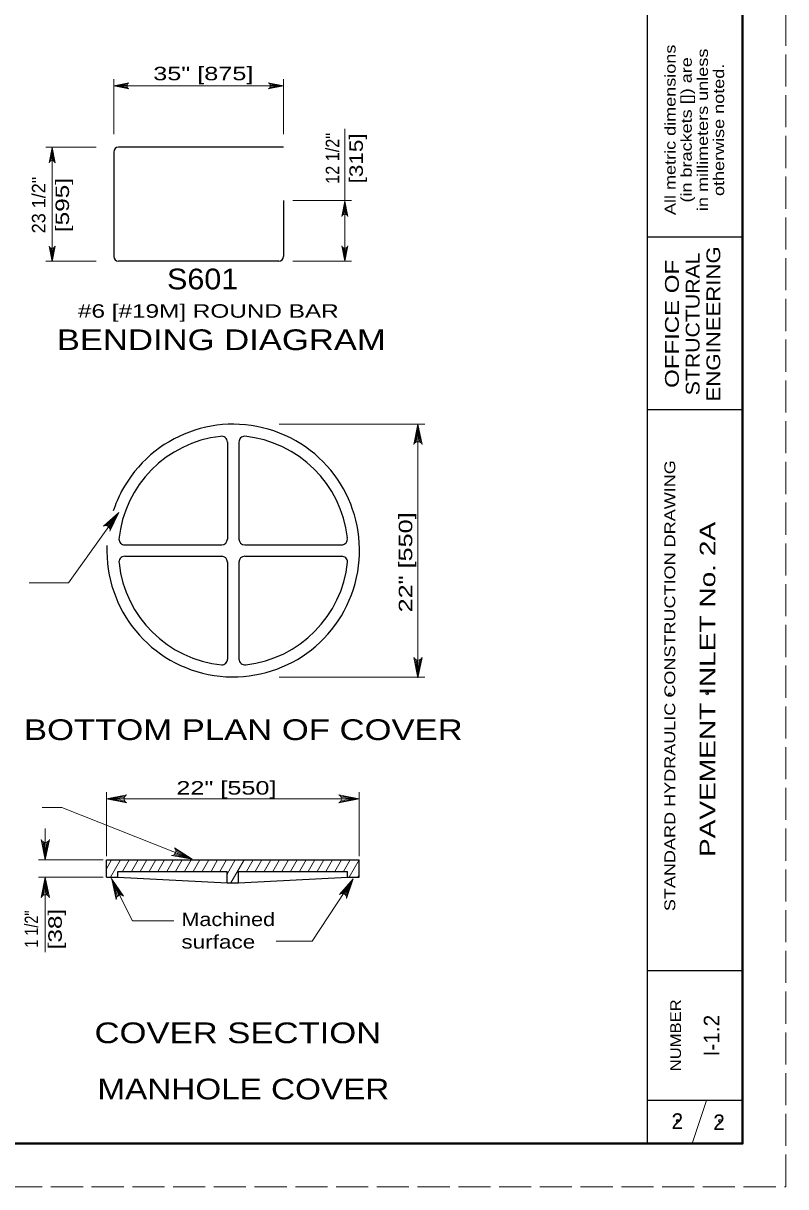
# Model space of a CAD drawing. Extents: x 758.3 to 792.3, y 849.7 to 893.7.
# Drawn here: x 783.49 to 792.32, y 849.69 to 863.16 of the extents above; entities that cross this region are included whole.
import ezdxf
from ezdxf.enums import TextEntityAlignment as Align

# ---------------------------------------------------------------- set-up
doc = ezdxf.new("R2010")
doc.units = 0
doc.header["$LTSCALE"] = 0.062
doc.header["$PDMODE"] = 32
doc.header["$PDSIZE"] = 0.031
doc.linetypes.add('LONG_DASHED', pattern=[7.5, 6, -1.5])
doc.layers.add('1', color=7, linetype='Continuous', lineweight=13)

msp = doc.modelspace()

# ---------------------------------------------------------------- linework, layer by layer
at = {"layer": '1', "lineweight": 25}
for p, q in [((790.7205, 850.18817), (790.7205, 871.18817)), ((791.8205, 871.18817), (791.8205, 850.18817)), ((786.50367, 861.72917), (784.59208, 861.72917)), ((784.53583, 861.67292), (784.53583, 860.46425)), ((786.50367, 861.11075), (786.50367, 860.46425)), ((791.8205, 860.68817), (790.7205, 860.68817)), ((786.44742, 860.40808), (784.59208, 860.40808)), ((791.8205, 858.68817), (790.7205, 858.68817)), ((785.85358, 858.314), (785.85358, 857.19033)), ((785.98658, 858.314), (785.98658, 857.1905)), ((784.66325, 857.12375), (785.78708, 857.12375)), ((786.05308, 857.12375), (787.17683, 857.12375)), ((784.66325, 856.99075), (785.78708, 856.99075)), ((786.05308, 856.99075), (787.17683, 856.99075)), ((785.85358, 856.92425), (785.85358, 855.80067)), ((785.98658, 856.92425), (785.98658, 855.80067)), ((784.45175, 853.27367), (784.45175, 853.47325)), ((784.45175, 853.47325), (787.37858, 853.47325)), ((787.37858, 853.27367), (787.37858, 853.47325)), ((784.45175, 853.27367), (784.58483, 853.27367)), ((784.58483, 853.27367), (784.58483, 853.34025)), ((784.58483, 853.34025), (785.84867, 853.34025)), ((784.58483, 853.27367), (785.84867, 853.20717)), ((785.84867, 853.20717), (785.84867, 853.34025)), ((785.98167, 853.20717), (785.98167, 853.34025)), ((785.98167, 853.34025), (787.2455, 853.34025)), ((785.98167, 853.20717), (787.2455, 853.27367)), ((787.2455, 853.27367), (787.2455, 853.34025)), ((787.2455, 853.27367), (787.37858, 853.27367)), ((785.84867, 853.20717), (785.98167, 853.20717)), ((791.8205, 852.18817), (790.7205, 852.18817)), ((791.8205, 850.68817), (790.7205, 850.68817))]:
    msp.add_line(p, q, dxfattribs=at)
at = {"layer": '1'}
for p, q in [((784.53583, 862.51583), (784.53583, 861.879)), ((786.50367, 862.51583), (786.50367, 861.879)), ((784.69608, 862.4625), (784.53583, 862.44008)), ((784.69067, 862.45142), (784.53583, 862.44008)), ((784.689, 862.44008), (784.53583, 862.44008)), ((784.69183, 862.42567), (784.53583, 862.44008)), ((784.698, 862.41533), (784.53583, 862.44008)), ((786.34158, 862.41533), (786.50367, 862.44008)), ((786.34342, 862.4625), (786.50367, 862.44008)), ((786.34767, 862.42567), (786.50367, 862.44008)), ((786.34883, 862.45142), (786.50367, 862.44008)), ((786.3505, 862.44008), (786.50367, 862.44008)), ((787.21333, 861.94258), (787.21333, 860.57067)), ((784.33358, 861.72917), (783.74917, 861.72917)), ((783.79758, 861.56442), (783.82233, 861.72658)), ((783.80792, 861.57058), (783.82233, 861.72658)), ((783.82233, 861.72658), (783.82233, 860.90492)), ((783.82233, 861.57342), (783.82233, 861.72658)), ((783.83367, 861.57175), (783.82233, 861.72658)), ((783.84475, 861.56633), (783.82233, 861.72658)), ((787.29033, 861.11075), (786.61192, 861.11075)), ((787.18858, 860.94342), (787.21333, 861.1055)), ((787.199, 860.9495), (787.21333, 861.1055)), ((787.21333, 860.95233), (787.21333, 861.1055)), ((787.22467, 860.95075), (787.21333, 861.1055)), ((787.23575, 860.94525), (787.21333, 861.1055)), ((783.82233, 860.90775), (783.82233, 860.4055)), ((783.79992, 860.56567), (783.82233, 860.4055)), ((783.811, 860.56025), (783.82233, 860.4055)), ((783.84708, 860.56758), (783.82233, 860.4055)), ((783.83675, 860.5615), (783.82233, 860.4055)), ((783.82233, 860.55867), (783.82233, 860.4055)), ((787.19092, 860.56833), (787.21333, 860.40808)), ((787.202, 860.56292), (787.21333, 860.40808)), ((787.21333, 860.59825), (787.21333, 860.40808)), ((787.23817, 860.57017), (787.21333, 860.40808)), ((787.22775, 860.56408), (787.21333, 860.40808)), ((787.21333, 860.56125), (787.21333, 860.40808)), ((784.33358, 860.40808), (783.74917, 860.40808)), ((787.29033, 860.40808), (786.61192, 860.40808)), ((786.454, 858.52183), (788.13925, 858.52183)), ((788.02758, 858.306), (788.06058, 858.52183)), ((788.04142, 858.31417), (788.06058, 858.52183)), ((788.06058, 858.52183), (788.06058, 856.47742)), ((788.06058, 858.31792), (788.06058, 858.52183)), ((788.07567, 858.31575), (788.06058, 858.52183)), ((788.09042, 858.3085), (788.06058, 858.52183)), ((784.43958, 857.34625), (784.59567, 857.49883)), ((784.45558, 857.34442), (784.59567, 857.49883)), ((784.47317, 857.33592), (784.59567, 857.49883)), ((784.48392, 857.32508), (784.59567, 857.49883)), ((784.49133, 857.3105), (784.59567, 857.49883)), ((788.06058, 856.51917), (788.06058, 855.58408)), ((788.03075, 855.79742), (788.06058, 855.58408)), ((788.0455, 855.79017), (788.06058, 855.58408)), ((788.09358, 855.79992), (788.06058, 855.58408)), ((788.07975, 855.79175), (788.06058, 855.58408)), ((788.06058, 855.788), (788.06058, 855.58408)), ((786.454, 855.59075), (788.13925, 855.59075)), ((784.45175, 853.51842), (784.45175, 854.25992)), ((784.45175, 853.92775), (784.45175, 854.23933)), ((784.665, 854.21108), (784.45175, 854.18125)), ((784.65783, 854.19633), (784.45175, 854.18125)), ((784.65558, 854.18125), (784.45175, 854.18125)), ((784.65942, 854.16208), (784.45175, 854.18125)), ((784.66758, 854.14825), (784.45175, 854.18125)), ((784.45175, 854.18125), (787.37858, 854.18125)), ((787.16275, 854.14825), (787.37858, 854.18125)), ((787.16525, 854.21108), (787.37858, 854.18125)), ((787.17092, 854.16208), (787.37858, 854.18125)), ((787.1725, 854.19633), (787.37858, 854.18125)), ((787.17475, 854.18125), (787.37858, 854.18125)), ((787.37858, 853.51842), (787.37858, 854.25992)), ((787.37858, 853.92775), (787.37858, 854.23933)), ((783.74375, 853.47325), (783.74375, 853.83683)), ((783.71392, 853.6865), (783.74375, 853.47325)), ((783.72867, 853.67933), (783.74375, 853.47325)), ((783.77675, 853.68908), (783.74375, 853.47325)), ((783.76292, 853.68092), (783.74375, 853.47325)), ((783.74375, 853.67708), (783.74375, 853.47325)), ((785.23367, 853.53233), (785.44325, 853.48258)), ((785.24583, 853.5435), (785.44325, 853.48258)), ((785.25333, 853.55675), (785.44325, 853.48258)), ((785.25425, 853.59183), (785.44325, 853.48258)), ((785.25683, 853.576), (785.44325, 853.48258)), ((784.413, 853.47325), (783.66508, 853.47325)), ((784.45217, 853.37142), (784.511, 853.47325)), ((784.49825, 853.27367), (784.61342, 853.47325)), ((784.63908, 853.34025), (784.71592, 853.47325)), ((784.74142, 853.34025), (784.81833, 853.47325)), ((784.84383, 853.34025), (784.92067, 853.47325)), ((784.94633, 853.34025), (785.02308, 853.47325)), ((785.04875, 853.34025), (785.12558, 853.47325)), ((785.15108, 853.34025), (785.22792, 853.47325)), ((785.2535, 853.34025), (785.33033, 853.47325)), ((785.356, 853.34025), (785.43275, 853.47325)), ((785.45833, 853.34025), (785.53508, 853.47325)), ((785.56075, 853.34025), (785.63758, 853.47325)), ((785.66317, 853.34025), (785.74, 853.47325)), ((785.7655, 853.34025), (785.84242, 853.47325)), ((785.84908, 853.30758), (785.94475, 853.47325)), ((785.89358, 853.20717), (786.04725, 853.47325)), ((786.07283, 853.34025), (786.14967, 853.47325)), ((786.17525, 853.34025), (786.252, 853.47325)), ((786.27767, 853.34025), (786.35442, 853.47325)), ((786.38008, 853.34025), (786.45692, 853.47325)), ((786.48242, 853.34025), (786.55925, 853.47325)), ((786.58483, 853.34025), (786.66167, 853.47325)), ((786.68733, 853.34025), (786.76408, 853.47325)), ((786.78967, 853.34025), (786.86658, 853.47325)), ((786.89208, 853.34025), (786.96892, 853.47325)), ((786.9945, 853.34025), (787.07142, 853.47325)), ((787.097, 853.34025), (787.17375, 853.47325)), ((787.19942, 853.34025), (787.27625, 853.47325)), ((787.26333, 853.27367), (787.37858, 853.47325)), ((784.413, 853.27367), (783.66508, 853.27367)), ((783.71075, 853.05792), (783.74375, 853.27367)), ((783.72458, 853.06608), (783.74375, 853.27367)), ((783.74375, 853.06983), (783.74375, 853.27367)), ((783.75883, 853.06767), (783.74375, 853.27367)), ((783.77358, 853.06042), (783.74375, 853.27367)), ((783.74375, 852.40442), (783.74375, 853.27367)), ((784.59525, 853.06367), (784.51267, 853.25008)), ((784.57933, 853.0525), (784.51267, 853.25008)), ((784.57, 853.03942), (784.51267, 853.25008)), ((784.61, 853.06783), (784.51267, 853.25008)), ((784.62642, 853.06717), (784.51267, 853.25008)), ((787.17417, 853.08442), (787.31175, 853.25392)), ((787.19017, 853.0845), (787.31175, 853.25392)), ((787.20858, 853.078), (787.31175, 853.25392)), ((787.2205, 853.0685), (787.31175, 853.25392)), ((787.22958, 853.05483), (787.31175, 853.25392)), ((787.36583, 853.27367), (787.379, 853.29667)), ((791.23717, 850.18817), (791.40383, 850.68817))]:
    msp.add_line(p, q, dxfattribs=at)
at = {"layer": '1', "linetype": 'LONG_DASHED'}
msp.add_lwpolyline([(758.3205, 849.68817), (792.3205, 849.68817), (792.3205, 871.68817), (758.3205, 871.68817)], close=True, dxfattribs=at)
at = {"layer": '1', "lineweight": 25}
msp.add_lwpolyline([(791.8205, 850.18817), (760.3205, 850.18817), (760.3205, 871.18817)], dxfattribs=at)
at = {"layer": '1', "lineweight": 40}
msp.add_lwpolyline([(760.3205, 871.18817), (791.8205, 871.18817), (791.8205, 850.18817), (760.3205, 850.18817)], close=True, dxfattribs=at)
at = {"layer": '1'}
for points in [[(784.71283, 862.40467), (784.53583, 862.44008), (784.71283, 862.4755)], [(786.50367, 862.44008), (785.87983, 862.44008), (784.53583, 862.44008)], [(786.32667, 862.40467), (786.50367, 862.44008), (786.32667, 862.4755)], [(783.78692, 861.54958), (783.82233, 861.72658), (783.85775, 861.54958)], [(787.178, 860.9285), (787.21333, 861.1055), (787.24875, 860.9285)], [(783.85775, 860.5825), (783.82233, 860.4055), (783.78692, 860.5825)], [(787.24875, 860.58508), (787.21333, 860.40808), (787.178, 860.58508)], [(788.0135, 858.28625), (788.06058, 858.52183), (788.10767, 858.28625)], [(784.59567, 857.49883), (784.01067, 856.68242), (783.557, 856.68242)], [(784.41642, 857.33892), (784.59567, 857.49883), (784.49175, 857.28225)], [(788.10767, 855.81967), (788.06058, 855.58408), (788.0135, 855.81967)], [(784.68733, 854.13417), (784.45175, 854.18125), (784.68733, 854.22833)], [(787.143, 854.13417), (787.37858, 854.18125), (787.143, 854.22833)], [(785.44325, 853.48258), (783.93508, 854.08192), (783.70817, 854.08192)], [(783.79083, 853.70883), (783.74375, 853.47325), (783.69667, 853.70883)], [(785.24092, 853.61217), (785.44325, 853.48258), (785.20667, 853.52442)], [(783.69667, 853.03817), (783.74375, 853.27367), (783.79083, 853.03817)], [(784.49825, 853.27367), (784.75425, 852.76983), (785.23308, 852.76983)], [(784.56508, 853.01558), (784.51267, 853.25008), (784.65125, 853.05383)], [(786.41775, 852.53342), (786.83367, 852.53342), (787.31175, 853.25392)], [(787.15192, 853.0745), (787.31175, 853.25392), (787.23317, 853.02683)]]:
    msp.add_lwpolyline(points, dxfattribs=at)
for centre, radius, start, end in [((784.72715, 862.44012), 0.0382, 112.08782, 247.91395), ((786.31239, 862.44012), 0.0382, 292.08605, 67.91218), ((783.82238, 861.53528), 0.0382, 22.08782, 157.91395), ((787.2134, 860.91424), 0.0382, 22.08782, 157.91395), ((783.8223, 860.59676), 0.0382, 202.08782, 337.91395), ((787.21332, 860.59936), 0.0382, 202.08782, 337.91395), ((788.06064, 858.2672), 0.05085, 22.08782, 157.91395), ((784.44269, 857.29534), 0.05085, 345.14514, 120.97127), ((788.06053, 855.83872), 0.05085, 202.08782, 337.91395), ((784.70637, 854.1813), 0.05085, 112.08782, 247.91395), ((787.12397, 854.1813), 0.05085, 292.08605, 67.91218), ((783.7437, 853.72786), 0.05085, 202.08782, 337.91395), ((785.20604, 853.57516), 0.05085, 270.75142, 46.57755), ((787.18298, 853.03423), 0.05085, 351.69068, 127.51681), ((783.74381, 853.0191), 0.05085, 22.08782, 157.91395), ((784.61591, 853.01733), 0.05085, 46.00055, 181.82668)]:
    msp.add_arc(centre, radius, start, end, dxfattribs=at)
at = {"layer": '1', "lineweight": 25}
for centre, major_axis, start_param, end_param in [((784.59208, 861.67296), (0.05622, 0), 1.57079628, 3.14159256), ((784.59208, 860.46428), (-0.05622, 0), 6.28318526, 7.85398154), ((786.44745, 860.46428), (0.05622, 0), 4.71238908, 6.28318536), ((785.92009, 857.05728), (1.46341, 0), 3.10225521, 8.93643561), ((785.92009, 857.05728), (1.33037, 0), 1.6813847, 3.04126085), ((785.78705, 858.31398), (0.06668, 0), 0.00000005, 1.77852023), ((786.05312, 858.31398), (0.06668, 0), 1.56753891, 3.14159265), ((785.92009, 857.05728), (1.33037, 0), 0.11058847, 1.47046447), ((785.92009, 857.05728), (1.46341, 0), 2.65325035, 2.82238808), ((784.66325, 857.1903), (-0.06668, 0), 6.27992896, 7.85398163), ((785.78705, 857.1903), (0.06652, 0), 4.71238908, 6.28318536), ((786.05312, 857.1903), (-0.06652, 0), 6.28318521, 7.85398149), ((787.17692, 857.1903), (0.06668, 0), 4.71238903, 6.49091027), ((784.66325, 856.92425), (0.06668, 0), 1.57079628, 3.34931752), ((785.78705, 856.92425), (0.06652, 0), 6.28318526, 7.85398154), ((786.05312, 856.92425), (0.06652, 0), 1.57079623, 3.14159251), ((787.17692, 856.92425), (0.06668, 0), 6.27992896, 7.85398163), ((785.92009, 857.05728), (1.33037, 0), 3.25218113, 4.61205713), ((785.92009, 857.05728), (1.33037, 0), 4.82297736, 6.1828535), ((785.78705, 855.80058), (-0.06668, 0), 1.56753891, 3.14159265), ((786.05312, 855.80058), (-0.06668, 0), 6.28318526, 8.06170544)]:
    msp.add_ellipse(centre, major_axis=major_axis, ratio=0.999895, start_param=start_param, end_param=end_param, dxfattribs=at)
at = {"layer": '1'}
for p in [(790.97792, 855.39417), (791.41075, 855.4015), (791.06858, 850.45192), (791.557, 850.45092)]:
    msp.add_point(p, dxfattribs=at)

# ---------------------------------------------------------------- texts
for s, height, width, p in [('All metric dimensions', 0.125, 1.25, (791.04433, 861.93025)), ('in millimeters unless', 0.125, 1.25, (791.41933, 861.93029)), ('(in brackets []) are', 0.125, 1.25, (791.23183, 861.93025)), ('otherwise noted.', 0.125, 1.25, (791.60683, 861.93025)), ('12 1/2"', 0.156, 0.9, (787.14817, 861.59992)), ('[315]', 0.156, 1.25, (787.42217, 861.59979)), ('[595]', 0.156, 1.35, (784.0185, 861.05912)), ('STRUCTURAL', 0.16, 1.15, (791.32225, 859.68262)), ('ENGINEERING', 0.16, 1.2, (791.56225, 859.68271)), ('OFFICE OF', 0.16, 1.3, (791.08225, 859.68262)), ('STANDARD HYDRAULIC CONSTRUCTION DRAWING', 0.125, 1.25, (791.04042, 855.49221)), ('PAVEMENT INLET No. 2A', 0.18, 1.35, (791.50425, 855.44833)), ('1 1/2"', 0.156, 0.8, (783.66058, 852.67275)), ('[38]', 0.156, 1.35, (783.93458, 852.67279)), ('NUMBER', 0.125, 1.15, (791.1075, 851.44225))]:
    msp.add_text(s, height=height, rotation=90, dxfattribs=dict(at, width=width)).set_placement(p, align=Align.CENTER)
for s, height, width, p in [('35" [875]', 0.156, 1.4, (785.57379, 862.50442)), ('S601', 0.24, 1.1, (785.566, 860.08258))]:
    msp.add_text(s, height=height, dxfattribs=dict(at, width=width)).set_placement(p, align=Align.CENTER)
for s, height, p in [('23 1/2"', 0.156, (783.7445, 861.05917)), ('I-1.2', 0.18, (791.55117, 851.4385))]:
    msp.add_text(s, height=height, rotation=90, dxfattribs=at).set_placement(p, align=Align.CENTER)
for s, height, width, p in [('#6 [#19M] ROUND BAR', 0.156, 1.35, (784.12192, 859.75408)), ('BENDING DIAGRAM', 0.24, 1.25, (783.87667, 859.37875)), ('BOTTOM PLAN OF COVER', 0.24, 1.25, (783.4965, 854.86217)), ('22" [550]', 0.156, 1.4, (785.26192, 854.2305)), ('Machined', 0.156, 1.2, (785.32033, 852.70758)), ('surface', 0.156, 1.25, (785.32033, 852.44692)), ('COVER SECTION', 0.24, 1.25, (784.31375, 851.35092)), ('MANHOLE COVER', 0.24, 1.2, (784.34725, 850.69983))]:
    msp.add_text(s, height=height, dxfattribs=dict(at, width=width)).set_placement(p)
at = {"layer": '1', "width": 1.4}
msp.add_text('22" [550]', height=0.156, rotation=90, dxfattribs=at).set_placement((787.99442, 856.34042))
at = {"layer": '1'}
for p in [(791.06496, 850.35825), (791.54779, 850.34567)]:
    msp.add_text('2', height=0.18, dxfattribs=at).set_placement(p, align=Align.CENTER)

doc.saveas('drawing.dxf')
